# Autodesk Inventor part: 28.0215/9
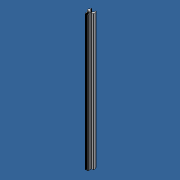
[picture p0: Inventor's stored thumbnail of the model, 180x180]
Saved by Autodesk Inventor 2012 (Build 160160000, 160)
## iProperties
Created: 2011-05
Part Number: 28.0215/9
Material: Aluminum-6061
Document SubType Name: Modeling
Designer: Administrator
Density: 2.71 g/cm^3
Mass: 148.638 g
Surface Area: 492.882 cm^2
Volume: 54.848 cm^3
Stock Number: 28.0002 SHAFT SUPP. PROFILE
Description: L = TRAVEL + 3.533"
Vendor: F
Translation Standard: STEP AP214CD
File Name: starvars.stp
Preprocessor: ACIS
Postprocessor: Build: 243, Release: 10 SP1 - Date: Mon 06/06/2005
Sent Units: MILLIMETERS
Uncertainty: 1e-06
Author: Administrator
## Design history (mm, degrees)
sketch "Sketch3"
  geometry: L1 (9.5, -0.5)-(9.5, -5.793); L2 (5.23, 0)-(9, 0); L3 (4.6, -0.318)-(5.08, -0.04); L4 (4.1, 0.3)-(4.15, -0.058); L5 (4.1, 4.3)-(4.1, 0.3); L6 (4.3, 4.56)-(4.1, 4.3); L7 (4.3, 6.5)-(4.3, 4.56); L8 (4.05, 9)-(4.3, 6.5); L9 (4.05, 9.598)-(4.05, 9); L10 (3.617, 10.75)-(3.849, 10.348); L11 (2.101, 11.5)-(2.318, 11.5); L12 (2.11, 11.319)-(2.101, 11.5); L13 (1.679, 11.008)-(2.06, 11.228); L14 (2.1, 10.591)-(1.679, 10.835); L15 (1.719, 10.198)-(2.1, 10.418); L16 (2.141, 9.782)-(1.72, 10.025); L17 (1.76, 9.389)-(2.141, 9.609); L18 (2.181, 8.973)-(1.76, 9.216); L19 (1.8, 8.579)-(2.181, 8.799); L20 (2.222, 8.163)-(1.8, 8.406); L21 (1.841, 7.77)-(2.222, 7.99); L22 (2.262, 7.354)-(1.841, 7.597); L23 (1.881, 6.961)-(2.262, 7.181); L24 (2.303, 6.544)-(1.881, 6.788); L25 (1.922, 6.151)-(2.303, 6.371); L26 (2.75, 5.5)-(1.922, 5.978); L27 (2.75, 4.165)-(2.75, 5.5); L28 (0.25, 4.742)-(2, 3.732); L29 (-2, 3.732)-(-0.25, 4.742); L30 (-2.75, 5.5)-(-2.75, 4.165); L31 (-1.922, 5.978)-(-2.75, 5.5); L32 (-2.303, 6.371)-(-1.922, 6.151); L33 (-1.881, 6.788)-(-2.303, 6.544); L34 (-2.262, 7.181)-(-1.881, 6.961); L35 (-1.841, 7.597)-(-2.262, 7.354); L36 (-2.222, 7.99)-(-1.841, 7.77); L37 (-1.8, 8.406)-(-2.222, 8.163); L38 (-2.181, 8.799)-(-1.8, 8.579); L39 (-1.76, 9.216)-(-2.181, 8.973); L40 (-2.141, 9.609)-(-1.76, 9.389); L41 (-1.72, 10.025)-(-2.141, 9.782); L42 (-2.1, 10.418)-(-1.72, 10.198); L43 (-1.679, 10.835)-(-2.1, 10.591); L44 (-2.06, 11.228)-(-1.679, 11.008); L45 (-2.101, 11.5)-(-2.11, 11.319); L46 (-2.318, 11.5)-(-2.101, 11.5); L47 (-3.849, 10.348)-(-3.617, 10.75); L48 (-4.05, 9)-(-4.05, 9.598); L49 (-4.3, 6.5)-(-4.05, 9); L50 (-4.3, 4.56)-(-4.3, 6.5); L51 (-4.1, 4.3)-(-4.3, 4.56); L52 (-4.1, 0.3)-(-4.1, 4.3); L53 (-4.15, -0.058)-(-4.1, 0.3); L54 (-5.08, -0.04)-(-4.6, -0.318); L55 (-9, 0)-(-5.23, 0); L56 (-9.5, -5.793)-(-9.5, -0.5); L57 (-8.51, -6.99)-(-9.354, -6.146); L58 (-7.798, -9.388)-(-8.38, -7.214); L59 (-6.066, -10.5)-(-6.349, -10.5); L60 (-6.079, -9)-(-5.978, -9.012); L61 (-4.786, -4.882)-(-4.876, -4.834); L62 (-3.834, -3.755)-(-3.783, -3.843); L63 (-2.6, 1.711)-(-2.6, -2.795); L64 (-0.25, 3.357)-(-2.35, 2.144)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; A1 r 0.5 centre (9, -5.793) between (9.354, -6.146) and (9.5, -5.793); A2 r 0.5 centre (9, -0.5) between (9.5, -0.5) and (9, 0); A3 r 0.3 centre (5.23, -0.3) between (5.23, 0) and (5.08, -0.04); A4 r 0.291 centre (4.441, -0.074) between (4.15, -0.058) and (4.6, -0.318); A5 r 1.5 centre (2.55, 9.598) between (4.05, 9.598) and (3.849, 10.348); A6 r 1.5 centre (2.318, 10) between (3.617, 10.75) and (2.318, 11.5); A7 r 0.1 centre (2.01, 11.314) between (2.06, 11.228) and (2.11, 11.319); A8 r 0.1 centre (1.729, 10.921) between (1.679, 11.008) and (1.679, 10.835); A9 r 0.1 centre (2.05, 10.505) between (2.1, 10.418) and (2.1, 10.591); A10 r 0.1 centre (1.769, 10.112) between (1.719, 10.198) and (1.72, 10.025); A11 r 0.1 centre (2.091, 9.695) between (2.141, 9.609) and (2.141, 9.782); A12 r 0.1 centre (1.81, 9.302) between (1.76, 9.389) and (1.76, 9.216); A13 r 0.1 centre (2.131, 8.886) between (2.181, 8.799) and (2.181, 8.973); A14 r 0.1 centre (1.85, 8.493) between (1.8, 8.579) and (1.8, 8.406); A15 r 0.1 centre (2.172, 8.077) between (2.222, 7.99) and (2.222, 8.163); A16 r 0.1 centre (1.891, 7.684) between (1.841, 7.77) and (1.841, 7.597); A17 r 0.1 centre (2.212, 7.267) between (2.262, 7.181) and (2.262, 7.354); A18 r 0.1 centre (1.931, 6.874) between (1.881, 6.961) and (1.881, 6.788); A19 r 0.1 centre (2.253, 6.458) between (2.303, 6.371) and (2.303, 6.544); A20 r 0.1 centre (1.972, 6.065) between (1.922, 6.151) and (1.922, 5.978); A21 r 0.5 centre (2.25, 4.165) between (2, 3.732) and (2.75, 4.165); A22 r 0.5 centre (0, 4.309) between (0.25, 4.742) and (-0.25, 4.742); A23 r 0.5 centre (-2.25, 4.165) between (-2.75, 4.165) and (-2, 3.732); A24 r 0.1 centre (-1.972, 6.065) between (-1.922, 5.978) and (-1.922, 6.151); A25 r 0.1 centre (-2.253, 6.458) between (-2.303, 6.544) and (-2.303, 6.371); A26 r 0.1 centre (-1.931, 6.874) between (-1.881, 6.788) and (-1.881, 6.961); A27 r 0.1 centre (-2.212, 7.267) between (-2.262, 7.354) and (-2.262, 7.181); A28 r 0.1 centre (-1.891, 7.684) between (-1.841, 7.597) and (-1.841, 7.77); A29 r 0.1 centre (-2.172, 8.077) between (-2.222, 8.163) and (-2.222, 7.99); A30 r 0.1 centre (-1.85, 8.493) between (-1.8, 8.406) and (-1.8, 8.579); A31 r 0.1 centre (-2.131, 8.886) between (-2.181, 8.973) and (-2.181, 8.799); A32 r 0.1 centre (-1.81, 9.302) between (-1.76, 9.216) and (-1.76, 9.389); A33 r 0.1 centre (-2.091, 9.695) between (-2.141, 9.782) and (-2.141, 9.609); A34 r 0.1 centre (-1.769, 10.112) between (-1.72, 10.025) and (-1.72, 10.198); A35 r 0.1 centre (-2.05, 10.505) between (-2.1, 10.591) and (-2.1, 10.418); A36 r 0.1 centre (-1.729, 10.921) between (-1.679, 10.835) and (-1.679, 11.008); A37 r 0.1 centre (-2.01, 11.314) between (-2.11, 11.319) and (-2.06, 11.228); A38 r 1.5 centre (-2.318, 10) between (-2.318, 11.5) and (-3.617, 10.75); A39 r 1.5 centre (-2.55, 9.598) between (-3.849, 10.348) and (-4.05, 9.598); A40 r 0.291 centre (-4.441, -0.074) between (-4.6, -0.318) and (-4.15, -0.058); A41 r 0.3 centre (-5.23, -0.3) between (-5.08, -0.04) and (-5.23, 0); A42 r 0.5 centre (-9, -0.5) between (-9, 0) and (-9.5, -0.5); A43 r 0.5 centre (-9, -5.793) between (-9.5, -5.793) and (-9.354, -6.146); A44 r 0.5 centre (-8.863, -7.344) between (-8.38, -7.214) and (-8.51, -6.99); A45 r 1.686 centre (-6.211, -8.82) between (-7.798, -9.388) and (-6.349, -10.5); A46 r 0.3 centre (-6.066, -10.2) between (-6.066, -10.5) and (-5.777, -10.119); A47 r 6 centre (0, -8.5) between (-5.978, -9.012) and (-5.777, -10.119); A48 r 6.1 centre (0, -8.5) between (-4.876, -4.834) and (-6.079, -9); A49 r 6 centre (0, -8.5) between (-3.783, -3.843) and (-4.786, -4.882); A50 r 6.1 centre (0, -8.5) between (-2.764, -3.062) and (-3.834, -3.755); A51 r 0.3 centre (-2.9, -2.795) between (-2.764, -3.062) and (-2.6, -2.795); A52 r 0.5 centre (-2.1, 1.711) between (-2.35, 2.144) and (-2.6, 1.711); A53 r 0.5 centre (0, 2.924) between (0.25, 3.357) and (-0.25, 3.357); A54 r 0.5 centre (2.1, 1.711) between (2.6, 1.711) and (2.35, 2.144); A55 r 0.3 centre (2.9, -2.795) between (2.6, -2.795) and (2.764, -3.062); A56 r 6.1 centre (0, -8.5) between (3.834, -3.755) and (2.764, -3.062); A57 r 6 centre (0, -8.5) between (4.786, -4.882) and (3.783, -3.843); A58 r 6.1 centre (0, -8.5) between (6.079, -9) and (4.876, -4.834); A59 r 6 centre (0, -8.5) between (5.777, -10.119) and (5.978, -9.012); A60 r 0.3 centre (6.066, -10.2) between (5.777, -10.119) and (6.066, -10.5); A61 r 1.686 centre (6.211, -8.82) between (6.349, -10.5) and (7.798, -9.388); A62 r 0.5 centre (8.863, -7.344) between (8.51, -6.99) and (8.38, -7.214); 2 further points
  constraints: 144 end point, 124 point on circle, 62 centre point
extrude "Extrusion1" new body sketch "Sketch3" stored distance "d1" = 394.546 (computed from TRAVEL); taper "d2" = 0 deg
body "Solid1"
other parameters: "TRAVEL" = 304.8 [user parameter; used in 1 equation term]
